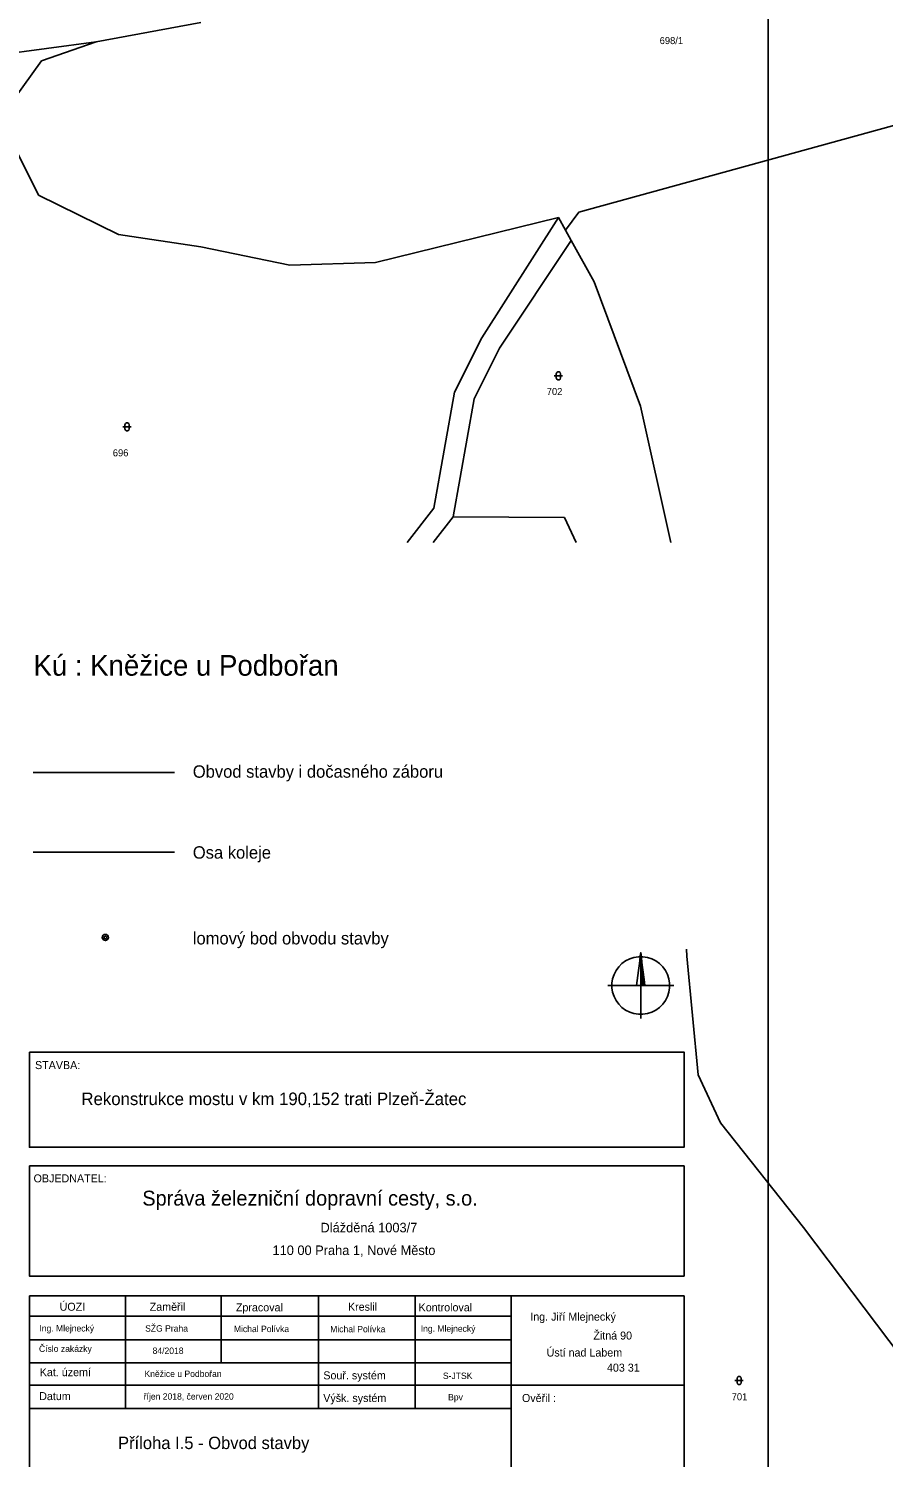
# Model space of a CAD drawing. Extents: x -812394 to -807601, y -1013097 to -1009266.
# Drawn here: x -809625.5 to -809418.3, y -1011159.4 to -1010813 of the extents above; entities that cross this region are included whole.
import ezdxf

# ---------------------------------------------------------------- set-up
doc = ezdxf.new("R2010")
doc.units = 0
for name, color, linetype in [('body', 7, 'Continuous'), ('Default', 7, 'Continuous'), ('KN_HRANICE', 7, 'Continuous'), ('KN_KULTURY', 7, 'Continuous'), ('KN_PARCELY', 7, 'Continuous'), ('LEGENDA', 7, 'Continuous'), ('tabulka', 7, 'Continuous')]:
    doc.layers.add(name, color=color, linetype=linetype)

# ---------------------------------------------------------------- blocks, each defined once
blk = doc.blocks.new('SEVER')
at = {"layer": 'Default'}
for points in [[(5.5, 69.8), (16.3, 68.1), (26.7, 64.7), (36.5, 59.7), (45.4, 53.2), (53.2, 45.4), (59.7, 36.5), (64.7, 26.7), (68.1, 16.3), (69.8, 5.5), (69.8, -5.5), (68.1, -16.3), (64.7, -26.7), (59.7, -36.5), (53.2, -45.4), (45.4, -53.2), (36.5, -59.7), (26.7, -64.7), (16.3, -68.1), (5.5, -69.8), (-5.5, -69.8), (-16.3, -68.1), (-26.7, -64.7), (-36.5, -59.7), (-45.4, -53.2), (-53.2, -45.4), (-59.7, -36.5), (-64.7, -26.7), (-68.1, -16.3), (-69.8, -5.5), (-69.8, 5.5), (-68.1, 16.3), (-64.7, 26.7), (-59.7, 36.5), (-53.2, 45.4), (-45.4, 53.2), (-36.5, 59.7), (-26.7, 64.7), (-16.3, 68.1), (-5.5, 69.8), (5.5, 69.8)], [(-10, 0), (-8.5, 12), (-7, 24), (-5.5, 36), (-4, 48), (-2.5, 60), (-1, 72), (0, 80), (1.5, 68), (3, 56), (4.5, 44), (6, 32), (7.5, 20), (9, 8), (10, 0), (9.2, 0.8), (9.2, 5.6), (8.4, 12), (8.4, 0.8), (7.6, 0.8), (7.6, 13.5), (7.6, 18.4), (6.8, 24.8), (6.8, 12.1), (6.8, 0.8), (6, 0.8), (6, 13.5), (6, 26.2), (6, 31.2), (5.2, 36.8), (5.2, 24.1), (5.2, 11.4), (5.2, 0.8), (4.4, 0.8), (4.4, 13.5), (4.4, 26.2), (4.4, 38.9), (4.4, 43.2), (3.6, 50.4), (3.6, 37.7), (3.6, 25), (3.6, 12.3), (3.6, 0.8), (2.8, 0.8), (2.8, 13.5), (2.8, 26.2), (2.8, 38.9), (2.8, 51.6), (2.8, 56), (2, 63.2), (2, 50.5), (2, 37.8), (2, 25.1), (2, 12.4), (2, 0.8), (1.2, 0.8), (1.2, 13.5), (1.2, 26.2), (1.2, 38.9), (1.2, 51.6), (1.2, 64.3), (1.2, 69.6), (0.4, 76), (0.4, 63.3), (0.4, 50.6), (0.4, 37.9), (0.4, 25.2), (0.4, 12.5), (0.4, 0.8)], [(0, 80), (0, 67.3), (0, 54.6), (0, 41.9), (0, 29.2), (0, 16.5), (0, 3.8), (0, -8.9), (0, -21.6), (0, -34.3), (0, -47), (0, -59.7), (0, -72.4), (0, -80)], [(80, 0), (67.3, 0), (54.6, 0), (41.9, 0), (29.2, 0), (16.5, 0), (3.8, 0), (-8.9, 0), (-21.6, 0), (-34.3, 0), (-47, 0), (-59.7, 0), (-72.4, 0), (-80, 0)]]:
    blk.add_lwpolyline(points, dxfattribs=at)
blk = doc.blocks.new('316')
at = {"layer": 'Default'}
for points in [[(-1, 1), (0.27, 1), (1, 1)], [(-0.5, 1.5), (-0.4, 1.79), (-0.15, 1.97), (0.16, 1.97), (0.41, 1.79), (0.51, 1.5), (0.51, 0.5), (0.41, 0.21), (0.16, 0.03), (-0.15, 0.03), (-0.4, 0.21), (-0.5, 0.5), (-0.5, 1.5)]]:
    blk.add_lwpolyline(points, dxfattribs=at)

msp = doc.modelspace()

# ---------------------------------------------------------------- linework, layer by layer
at = {"layer": 'body'}
for radius in [0.75, 0.35]:
    msp.add_circle((-809606.87, -1011033.36), radius, dxfattribs=at)
at = {"layer": 'KN_HRANICE'}
for p, q in [((-809609.07, -1010816.23), (-809583.77, -1010811.56)), ((-809705.08, -1010829.3), (-809609.07, -1010816.23)), ((-809609.07, -1010816.23), (-809622.36, -1010820.88)), ((-809622.36, -1010820.88), (-809629.15, -1010830.35)), ((-809381.38, -1010827.1), (-809492.16, -1010857.54)), ((-809628.52, -1010842.52), (-809623.05, -1010853.45)), ((-809603.73, -1010862.94), (-809623.05, -1010853.45)), ((-809492.16, -1010857.54), (-809495.34, -1010861.89)), ((-809497.02, -1010858.87), (-809541.42, -1010869.76)), ((-809497.02, -1010858.87), (-809515.67, -1010887.99)), ((-809495.34, -1010861.89), (-809497.02, -1010858.87)), ((-809493.94, -1010864.41), (-809495.34, -1010861.89)), ((-809583.78, -1010865.98), (-809603.73, -1010862.94)), ((-809511.33, -1010890.51), (-809493.94, -1010864.41)), ((-809493.94, -1010864.41), (-809488.39, -1010874.4)), ((-809562.13, -1010870.38), (-809583.78, -1010865.98)), ((-809541.42, -1010869.76), (-809562.13, -1010870.38)), ((-809488.39, -1010874.4), (-809477.19, -1010904.54)), ((-809515.67, -1010887.99), (-809522.26, -1010901.18)), ((-809517.46, -1010902.78), (-809511.33, -1010890.51)), ((-809522.26, -1010901.18), (-809527.3, -1010929.3)), ((-809522.6, -1010931.38), (-809517.46, -1010902.78)), ((-809477.19, -1010904.54), (-809469.8, -1010937.64)), ((-809527.3, -1010929.3), (-809533.71, -1010937.64)), ((-809527.41, -1010937.64), (-809522.6, -1010931.38)), ((-809495.6, -1010931.58), (-809522.6, -1010931.38)), ((-809495.6, -1010931.58), (-809492.76, -1010937.64)), ((-809466.04, -1011036.22), (-809465.93, -1011037.86)), ((-809465.93, -1011037.86), (-809463.23, -1011066.67)), ((-809463.23, -1011066.67), (-809457.81, -1011078.32)), ((-809457.81, -1011078.32), (-809437.7, -1011103.69)), ((-809437.7, -1011103.69), (-809413.98, -1011135.02))]:
    msp.add_line(p, q, dxfattribs=at)
at = {"layer": 'LEGENDA'}
for p, q in [((-809624.34, -1010993.39), (-809590.14, -1010993.39)), ((-809624.34, -1011012.68), (-809590.14, -1011012.68))]:
    msp.add_line(p, q, dxfattribs=at)
msp.add_lwpolyline([(-810040.19, -1011186.89), (-809446.19, -1011186.89), (-809446.19, -1010766.89), (-810040.19, -1010766.89)], close=True, dxfattribs=at)
at = {"layer": 'tabulka'}
for p, q in [((-809625.27, -1011120.25), (-809466.62, -1011120.25)), ((-809601.98, -1011120.25), (-809601.98, -1011147.57)), ((-809578.83, -1011120.25), (-809578.83, -1011136.45)), ((-809555.24, -1011120.25), (-809555.24, -1011147.57)), ((-809531.79, -1011120.25), (-809531.79, -1011147.57)), ((-809508.49, -1011175.38), (-809508.49, -1011120.25)), ((-809625.27, -1011125.16), (-809508.49, -1011125.16)), ((-809625.27, -1011130.87), (-809508.49, -1011130.87)), ((-809625.27, -1011136.45), (-809508.49, -1011136.45)), ((-809625.27, -1011141.87), (-809466.62, -1011141.87)), ((-809625.27, -1011147.57), (-809508.49, -1011147.57))]:
    msp.add_line(p, q, dxfattribs=at)
for points in [[(-809625.27, -1011061.16), (-809466.62, -1011061.16), (-809466.62, -1011084.23), (-809625.27, -1011084.23)], [(-809625.27, -1011088.75), (-809466.62, -1011088.75), (-809466.62, -1011115.44), (-809625.27, -1011115.44)]]:
    msp.add_lwpolyline(points, close=True, dxfattribs=at)
msp.add_lwpolyline([(-809466.62, -1011120.25), (-809466.62, -1011175.38), (-809625.27, -1011175.38), (-809625.27, -1011120.25)], dxfattribs=at)

# ---------------------------------------------------------------- block references
at = {"layer": 'KN_KULTURY'}
for p in [(-809497.08, -1010898.24), (-809601.64, -1010910.6), (-809453.28, -1011141.77)]:
    msp.add_blockref('316', p, dxfattribs=at)
at = {"layer": 'LEGENDA', "xscale": 0.1, "yscale": 0.10000000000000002}
msp.add_blockref('SEVER', (-809477.12, -1011045.01), dxfattribs=at)

# ---------------------------------------------------------------- texts
at = {"layer": 'KN_PARCELY'}
for s, p in [('698/1', (-809472.53, -1010816.81)), ('702', (-809499.9, -1010901.87)), ('696', (-809605.08, -1010916.74)), ('701', (-809455.07, -1011145.55))]:
    msp.add_text(s, height=1.7, dxfattribs=at).set_placement(p)
at = {"layer": 'LEGENDA'}
for s, height, p in [('Kú : Kněžice u Podbořan', 5, (-809624.31, -1010969.91)), ('Obvod stavby i dočasného záboru', 3, (-809585.69, -1010994.64)), ('Osa koleje', 3, (-809585.69, -1011014.26)), ('lomový bod obvodu stavby', 3, (-809585.69, -1011035.06)), ('Rekonstrukce mostu v km 190,152 trati Plzeň-Žatec', 3.04, (-809612.68, -1011074))]:
    msp.add_text(s, height=height, dxfattribs=at).set_placement(p)
at = {"layer": 'tabulka'}
for s, height, p in [('STAVBA:', 1.94, (-809623.93, -1011065.27)), ('OBJEDNATEL:', 1.94, (-809624.28, -1011092.73)), ('Správa železniční dopravní cesty, s.o.', 3.61, (-809597.93, -1011098.36)), ('Dlážděná 1003/7', 2.32, (-809554.73, -1011104.85)), ('110 00 Praha 1, Nové Město', 2.32, (-809566.37, -1011110.35)), ('ÚOZI', 1.94, (-809617.97, -1011123.85)), ('Zaměřil', 1.94, (-809596.13, -1011123.85)), ('Kreslil', 1.94, (-809548.08, -1011123.85)), ('Zpracoval', 1.94, (-809575.24, -1011124)), ('Kontroloval', 1.94, (-809530.96, -1011124)), ('Ing. Jiří Mlejnecký', 1.94, (-809503.89, -1011126.25)), ('Ing. Mlejnecký', 1.552, (-809622.87, -1011128.88)), ('SŽG Praha', 1.552, (-809597.24, -1011128.91)), ('Michal Polívka', 1.552, (-809575.72, -1011129.03)), ('Michal Polívka', 1.552, (-809552.39, -1011129.07)), ('Ing. Mlejnecký', 1.552, (-809530.44, -1011128.95)), ('Žitná 90', 1.94, (-809488.6, -1011130.83)), ('Číslo zakázky', 1.552, (-809622.97, -1011133.83)), ('84/2018', 1.552, (-809595.43, -1011134.32)), ('Ústí nad Labem', 1.94, (-809499.93, -1011134.95)), ('Kat. území', 1.94, (-809622.78, -1011139.71)), ('Kněžice u Podbořan', 1.552, (-809597.4, -1011139.91)), ('Souř. systém', 1.94, (-809554.05, -1011140.48)), ('S-JTSK', 1.552, (-809525.06, -1011140.39)), ('403 31', 1.94, (-809485.3, -1011138.61)), ('Datum', 1.94, (-809622.92, -1011145.51)), ('říjen 2018, červen 2020', 1.552, (-809597.58, -1011145.4)), ('Výšk. systém', 1.94, (-809554.07, -1011145.97)), ('Bpv', 1.552, (-809523.8, -1011145.58)), ('Ověřil :', 1.94, (-809505.9, -1011145.97)), ('Příloha I.5 - Obvod stavby', 3, (-809603.81, -1011157.38))]:
    msp.add_text(s, height=height, dxfattribs=at).set_placement(p)

doc.saveas('drawing.dxf')
